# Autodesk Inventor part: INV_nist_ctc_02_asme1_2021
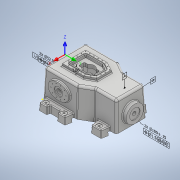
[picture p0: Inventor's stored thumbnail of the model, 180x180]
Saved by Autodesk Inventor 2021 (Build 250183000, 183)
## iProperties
Created: 2016-11
Part Number: INV_nist_ctc_02_asme1_2021
Material: Generic
Document SubType Name: Modeling
Designer: t_liuje
Density: 1 g/cm^3
Appearance: Default
Author: t_liuje
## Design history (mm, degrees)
node "Coaxial Axes Pattern 1"
node "Coaxial Axes Pattern 2"
  node "Simple Hole 17"
  node "Simple Hole 18"
  node "Hole Note 14"
  node "Feature Control Frame 49"
node "Coplanar Group 1" dims "d446" = 2.3385 (derived), "d447" = 8.09976 (derived), "d525" = 52.99059 (derived), "d527" = 0.05 (derived), "d528" = 0 (derived), "d529" = 0 (derived), "d545" = 21.5915 (derived), "d547" = 0.05 (derived), "d548" = 0 (derived), "d549" = 0 (derived), "d560" = 7.29892 (derived), "d561" = 5.22182 (derived), "d562" = 0.5 (derived), "d563" = 0 (derived), "d564" = 0 (derived), "d565" = 4.43129 (derived), "d566" = 0.05984 (derived), "d567" = 0.5 (derived), "d568" = 0 (derived), "d569" = 0 (derived), "d570" = 3.72166 (derived), "d571" = 0.83718 (derived), "d572" = 0.5 (derived), "d573" = 0 (derived)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
  node "Planar Surface 24"
  node "Planar Surface 25"
  node "Planar Surface 26"
  node "Planar Surface 27"
  node "Feature Control Frame 52"
  node "Datum Identifier 26" dims "d446" = 2.3385 (derived), "d447" = 8.09976 (derived), "d525" = 52.99059 (derived), "d527" = 0.05 (derived), "d528" = 0 (derived), "d529" = 0 (derived), "d545" = 21.5915 (derived), "d547" = 0.05 (derived), "d548" = 0 (derived), "d549" = 0 (derived), "d560" = 7.29892 (derived), "d561" = 5.22182 (derived), "d562" = 0.5 (derived), "d563" = 0 (derived), "d564" = 0 (derived), "d565" = 4.43129 (derived), "d566" = 0.05984 (derived), "d567" = 0.5 (derived), "d568" = 0 (derived), "d569" = 0 (derived), "d570" = 3.72166 (derived), "d571" = 0.83718 (derived), "d572" = 0.5 (derived), "d573" = 0 (derived)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
  node "Leader Text 1"
node "Datum Reference Frame 28"
node "Simple Hole 19" dims "d446" = 2.3385 (derived), "d447" = 8.09976 (derived), "d525" = 52.99059 (derived), "d527" = 0.05 (derived), "d528" = 0 (derived), "d529" = 0 (derived), "d545" = 21.5915 (derived), "d547" = 0.05 (derived), "d548" = 0 (derived), "d549" = 0 (derived), "d560" = 7.29892 (derived), "d561" = 5.22182 (derived), "d562" = 0.5 (derived), "d563" = 0 (derived), "d564" = 0 (derived), "d565" = 4.43129 (derived), "d566" = 0.05984 (derived), "d567" = 0.5 (derived), "d568" = 0 (derived), "d569" = 0 (derived), "d570" = 3.72166 (derived), "d571" = 0.83718 (derived), "d572" = 0.5 (derived), "d573" = 0 (derived)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
  node "Feature Control Frame 60"
  node "Datum Identifier 30" dims "d446" = 2.3385 (derived), "d447" = 8.09976 (derived), "d525" = 52.99059 (derived), "d527" = 0.05 (derived), "d528" = 0 (derived), "d529" = 0 (derived), "d545" = 21.5915 (derived), "d547" = 0.05 (derived), "d548" = 0 (derived), "d549" = 0 (derived), "d560" = 7.29892 (derived), "d561" = 5.22182 (derived), "d562" = 0.5 (derived), "d563" = 0 (derived), "d564" = 0 (derived), "d565" = 4.43129 (derived), "d566" = 0.05984 (derived), "d567" = 0.5 (derived), "d568" = 0 (derived), "d569" = 0 (derived), "d570" = 3.72166 (derived), "d571" = 0.83718 (derived), "d572" = 0.5 (derived), "d573" = 0 (derived)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
node "Datum Reference Frame 29"
node "Datum Reference Frame 30"
node "Simple Hole 20" dims "d446" = 2.3385 (derived), "d447" = 8.09976 (derived), "d525" = 52.99059 (derived), "d527" = 0.05 (derived), "d528" = 0 (derived), "d529" = 0 (derived), "d545" = 21.5915 (derived), "d547" = 0.05 (derived), "d548" = 0 (derived), "d549" = 0 (derived), "d560" = 7.29892 (derived), "d561" = 5.22182 (derived), "d562" = 0.5 (derived), "d563" = 0 (derived), "d564" = 0 (derived), "d565" = 4.43129 (derived), "d566" = 0.05984 (derived), "d567" = 0.5 (derived), "d568" = 0 (derived), "d569" = 0 (derived), "d570" = 3.72166 (derived), "d571" = 0.83718 (derived), "d572" = 0.5 (derived), "d573" = 0 (derived)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
  node "Feature Control Frame 61"
  node "Datum Identifier 31" dims "d446" = 2.3385 (derived), "d447" = 8.09976 (derived), "d525" = 52.99059 (derived), "d527" = 0.05 (derived), "d528" = 0 (derived), "d529" = 0 (derived), "d545" = 21.5915 (derived), "d547" = 0.05 (derived), "d548" = 0 (derived), "d549" = 0 (derived), "d560" = 7.29892 (derived), "d561" = 5.22182 (derived), "d562" = 0.5 (derived), "d563" = 0 (derived), "d564" = 0 (derived), "d565" = 4.43129 (derived), "d566" = 0.05984 (derived), "d567" = 0.5 (derived), "d568" = 0 (derived), "d569" = 0 (derived), "d570" = 3.72166 (derived), "d571" = 0.83718 (derived), "d572" = 0.5 (derived), "d573" = 0 (derived)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
node "Datum Reference Frame 31"
node "Datum Reference Frame 33"
node "Datum Reference Frame 35"
node "Datum Reference Frame 32"
node "Datum Reference Frame 34"
node "Planar Surface 28"
  node "Feature Control Frame 55"
node "Planar Surface 29"
  node "Feature Control Frame 56"
node "Planar Surface 30"
  node "Feature Control Frame 58"
node "Planar Surface 31"
  node "Feature Control Frame 59"
body "Solid1"
node "Blocks"
node "Annotations"
node "Tolerance Features"
sketch "Sketch1"
  geometry: L1 (0, 0)-(400, 0); L2 (400, 500)-(0, 500); L3 (0, 500)-(0, 0); L4 (529.904, 425)-(780, 425); L5 (780, 425)-(780, 75); L6 (780, 75)-(529.904, 75); L7 (400, 500)-(529.904, 425); L8 (400, 0)-(529.904, 75)
  constraints: 16 end point, 3 parallel, 2 horizontal, 1 perpendicular, 1 vertical
  dimensions: "d0" = 400 distance of L2.end L2.start; "d3" = 350 distance of L4.end L5.end; "d4" = 75 distance between parallel lines of L1 L6; "d5" = 150 deg angle of L2 L7; "d6" = 150 deg angle of L1 L8 (= d5); "d8" = 500 distance of L2.end L1.start; "d9" = 380 distance from line of L5 L2.start
extrude "Extrusion1" new body sketch "Sketch1" distance "d10" = 330; taper "d11" = 0 deg
feature "FaceDraft1" dims angle "d12" = -2 deg
shell "Shell1" dims "d171" = 40
fillet "Fillet1" dims "d670" = 25
sketch "Sketch2"
  geometry: L1 (115, 385)-(365, 385); L2 (465, 332.499)-(465, 167.501); L3 (365, 115)-(115, 115); L4 (115, 115)-(115, 385); L5 (0, 0)-(400, 0) reference; L6 (0, 500)-(0, 0) reference; L7 (365, 385)-(465, 332.499); L8 (365, 115)-(465, 167.501); L9 (353.905, 340)-(160, 340); L10 (160, 340)-(160, 160); L11 (160, 160)-(353.905, 160); L12 (353.905, 160)-(420, 194.7); L13 (420, 194.7)-(420, 305.3); L14 (420, 305.3)-(353.905, 340); 4 further points
  constraints: 24 end point, 4 parallel, 2 perpendicular, 1 horizontal, 5 other
  dimensions: "d16" = 115 distance between parallel lines of L5 L3; "d17" = 115 distance between parallel lines of L6 L4; "d18" = 100 distance from line of L1.end L2; "d19" = 152.3 deg angle of L1 L7; "d22" = 270 distance between parallel lines of L1 L3; "d23" = 350 distance between parallel lines of L4 L2; "d24" = 152.3 deg angle of L3 L8; "d25" = 100 distance from line of L2 L3.start (= d18); "d26" = 45 distance between parallel lines of L1 L9
extrude "Extrusion2" join sketch "Sketch2" distance "d27" = 30; taper "d28" = 0 deg
fillet "Fillet2" dims "d29" = 8
sketch "Sketch3"
  geometry: L1 (355.652, 339.083)-(415.719, 307.547) reference; L2 (420, 300.464)-(420, 199.536) reference; L3 (415.719, 192.453)-(355.652, 160.917) reference; L4 (351.933, 160)-(168, 160) reference; L5 (160, 168)-(160, 332) reference; L6 (168, 340)-(351.933, 340) reference; L7 (365, 385)-(115, 385) reference; L8 (115, 385)-(115, 115) reference; L9 (115, 115)-(365, 115) reference; L10 (365, 115)-(465, 167.501) reference; L11 (465, 167.501)-(465, 332.499) reference; L12 (465, 332.499)-(365, 385) reference; L13 (351.933, 351)-(168, 351); L14 (149, 332)-(149, 168); L15 (168, 149)-(351.933, 149); L16 (360.765, 151.178)-(420.832, 182.713); L17 (431, 199.536)-(431, 300.464); L18 (420.832, 317.287)-(360.765, 348.822); L19 (168, 359)-(351.933, 359); L20 (364.484, 355.906)-(424.551, 324.37); L21 (439, 300.464)-(439, 199.536); L22 (424.551, 175.63)-(364.484, 144.094); L23 (351.933, 141)-(168, 141); L24 (141, 168)-(141, 332); A1 r 8 centre (412, 300.464) between (420, 300.464) and (415.719, 307.547) reference; A2 r 8 centre (412, 199.536) between (415.719, 192.453) and (420, 199.536) reference; A3 r 8 centre (351.933, 168) between (351.933, 160) and (355.652, 160.917) reference; A4 r 8 centre (168, 168) between (160, 168) and (168, 160) reference; A5 r 8 centre (168, 332) between (168, 340) and (160, 332) reference; A6 r 8 centre (351.933, 332) between (355.652, 339.083) and (351.933, 340) reference; A7 r 19 centre (168, 332) between (168, 351) and (149, 332); A8 r 19 centre (168, 168) between (149, 168) and (168, 149); A9 r 19 centre (351.933, 168) between (351.933, 149) and (360.765, 151.178); A10 r 19 centre (412, 199.536) between (420.832, 182.713) and (431, 199.536); A11 r 19 centre (412, 300.464) between (431, 300.464) and (420.832, 317.287); A12 r 19 centre (351.933, 332) between (360.765, 348.822) and (351.933, 351); A13 r 27 centre (351.933, 332) between (364.484, 355.906) and (351.933, 359); A14 r 27 centre (412, 300.464) between (439, 300.464) and (424.551, 324.37); A15 r 27 centre (412, 199.536) between (424.551, 175.63) and (439, 199.536); A16 r 27 centre (351.933, 168) between (351.933, 141) and (364.484, 144.094); A17 r 27 centre (168, 168) between (141, 168) and (168, 141); A18 r 27 centre (168, 332) between (168, 359) and (141, 332); 1 further point
  constraints: 24 end point, 24 point on circle, 12 centre point, 22 other
  dimensions: "d30" = 11 distance between parallel lines of L6 L13; "d31" = 8 distance between parallel lines of L13 L19
extrude "Extrusion3" cut sketch "Sketch3" distance "d32" = 8; taper "d33" = 0 deg
hole "Hole1" diameter "d36" = 8.38; stored, may be unused: countersink angle "d40" = 90 deg, drill point angle "d42" = 0 deg; dims "d34" = 13, "d35" = 13, "d37" = 6, "d38" = 4, "d39" = 2, "d41" = 25
hole "Hole2" diameter "d51" = 8.38; stored, may be unused: countersink angle "d55" = 90 deg, drill point angle "d57" = 0 deg; dims "d49" = 61, "d50" = 13, "d52" = 6, "d53" = 4, "d54" = 2, "d56" = 25
hole "Hole3" diameter "d60" = 8.38; stored, may be unused: countersink angle "d64" = 90 deg, drill point angle "d66" = 0 deg; dims "d58" = 13, "d59" = 110, "d61" = 6, "d62" = 4, "d63" = 2, "d65" = 25
hole "Hole4" diameter "d69" = 8.38; stored, may be unused: countersink angle "d73" = 90 deg, drill point angle "d75" = 0 deg; dims "d67" = 13, "d68" = 160, "d70" = 6, "d71" = 4, "d72" = 2, "d74" = 25
hole "Hole5" diameter "d78" = 8.38; stored, may be unused: countersink angle "d82" = 90 deg, drill point angle "d84" = 0 deg; dims "d76" = 13, "d77" = 61, "d79" = 6, "d80" = 4, "d81" = 2, "d83" = 25
pattern_linear "Rectangular Pattern3" dims "d87" = 48
hole "Hole6" diameter "d90" = 8.38; stored, may be unused: countersink angle "d94" = 90 deg, drill point angle "d96" = 0 deg; dims "d88" = 13, "d89" = 13, "d91" = 6, "d92" = 4, "d93" = 2, "d95" = 25
hole "Hole7" diameter "d99" = 8.38; stored, may be unused: countersink angle "d103" = 90 deg, drill point angle "d105" = 0 deg; dims "d97" = 13, "d98" = 13, "d100" = 6, "d101" = 4, "d102" = 2, "d104" = 25
pattern_linear "Rectangular Pattern4" dims "d117" = 50.9055
hole "Hole9" diameter "d120" = 8.38; stored, may be unused: countersink angle "d124" = 90 deg, drill point angle "d126" = 0 deg; dims "d118" = 13, "d119" = 61, "d121" = 6, "d122" = 4, "d123" = 2, "d125" = 25
pattern_linear "Rectangular Pattern5" dims "d129" = 48
hole "Hole10" diameter "d132" = 8.38; stored, may be unused: countersink angle "d136" = 90 deg, drill point angle "d138" = 0 deg; dims "d130" = 13, "d131" = 13, "d133" = 6, "d134" = 4, "d135" = 2, "d137" = 25
hole "Hole11" diameter "d141" = 8.38; stored, may be unused: countersink angle "d145" = 90 deg, drill point angle "d147" = 0 deg; dims "d139" = 13, "d140" = 13, "d142" = 6, "d143" = 4, "d144" = 2, "d146" = 25
pattern_linear "Rectangular Pattern6" dims "d150" = 50.9055
hole "Hole12" diameter "d153" = 8.38; stored, may be unused: countersink angle "d157" = 90 deg, drill point angle "d159" = 0 deg; dims "d151" = 13, "d152" = 65, "d154" = 6, "d155" = 4, "d156" = 2, "d158" = 25
hole "Hole13" diameter "d162" = 8.38; stored, may be unused: countersink angle "d166" = 90 deg, drill point angle "d168" = 0 deg; dims "d160" = 13, "d161" = 65, "d163" = 6, "d164" = 4, "d165" = 2, "d167" = 25
feature "FaceDraft2" dims angle "d169" = 2 deg
feature "FaceDraft3" dims angle "d170" = 2 deg
fillet "Fillet3" dims "d172" = 25
sketch "Sketch5"
  geometry: L1 (0.093, 195.706)-(0.093, 155.706); L2 (180.093, 155.706)-(180.093, 195.706); L3 (180.093, 210.706)-(0.093, 140.706); L4 (0.093, 210.706)-(180.093, 140.706); L5 (380.093, 400.722)-(380.093, -74.294) reference; L6 (380.093, -74.294)-(-13.212, -74.294) reference; L7 (15.093, 140.706)-(41.359, 140.706); L8 (138.827, 140.706)-(165.093, 140.706); L9 (165.093, 210.706)-(138.827, 210.706); L10 (41.359, 210.706)-(15.093, 210.706); A1 r 60 centre (90.093, 175.706) between (138.827, 210.706) and (41.359, 210.706); A2 r 60 centre (90.093, 175.706) between (41.359, 140.706) and (138.827, 140.706); A3 r 15 centre (165.093, 155.706) between (165.093, 140.706) and (180.093, 155.706); A4 r 15 centre (165.093, 195.706) between (180.093, 195.706) and (165.093, 210.706); A5 r 15 centre (15.093, 195.706) between (15.093, 210.706) and (0.093, 195.706); A6 r 15 centre (15.093, 155.706) between (0.093, 155.706) and (15.093, 140.706); 5 further points
  constraints: 16 end point, 12 point on circle, 8 point on line, 8 tangent, 6 centre point, 5 parallel, 2 equal radius, 2 horizontal, 2 midpoint, 2 perpendicular, 1 coincident
  dimensions: "d173" = 180 distance of L4.end L3.end; "d174" = 70 distance of L3.end L4.start; "d175" = 200 distance between parallel lines of L2 L5; "d178" = 15 radius of A3; "d179" = 15 radius of A6 (derived)
extrude "Extrusion4" cut sketch "Sketch5" stored distance "d180" = 8; taper "d181" = 0 deg
workplane "Work Plane2"
workplane "Work Plane4"
sketch "Sketch6"
  geometry: L1 (99.985, 0)-(400.015, 0) reference; C1 r 100 at (250, 140); 3 further points
  constraints: 1 centre point
  dimensions: "d186" = 200 diameter of C1; "d187" = 140 distance from line of L1 C1.centre; "d188" = 250 horizontal distance of point (0, 0) C1.centre
extrude "Extrusion5" join sketch "Sketch6" stored distance "d189" = 8; taper "d190" = 0 deg
sketch "Sketch7"
  geometry: L1 (475.015, 0)-(0, 0) reference; C1 r 100 at (250, 140); 2 further points
  constraints: 1 centre point
  dimensions: "d191" = 200 diameter of C1; "d192" = 250 horizontal distance of C1.centre L1.end; "d193" = 140 distance from line of C1.centre L1
extrude "Extrusion6" join sketch "Sketch7" stored distance "d194" = 8; taper "d195" = 0 deg
hole "Hole14" diameter "d198" = 120; stored, may be unused: countersink angle "d202" = 90 deg, drill point angle "d204" = 0 deg; dims "d196" = 10, "d197" = 10, "d199" = 6, "d200" = 4, "d201" = 2, "d203" = 8
hole "Hole15" diameter "d207" = 120; stored, may be unused: countersink angle "d211" = 90 deg, drill point angle "d213" = 0 deg; dims "d205" = 10, "d206" = 10, "d208" = 6, "d209" = 4, "d210" = 2, "d212" = 8
hole "Hole16" diameter "d216" = 40; stored, may be unused: countersink angle "d220" = 90 deg, drill point angle "d222" = 0 deg; dims "d217" = 6, "d218" = 4, "d219" = 2, "d221" = 8, "d722" = 10, "d723" = 10
hole "Hole17" diameter "d225" = 117; stored, may be unused: countersink angle "d229" = 90 deg, drill point angle "d231" = 0 deg; dims "d226" = 6, "d227" = 4, "d228" = 2, "d230" = 18, "d241" = 10, "d242" = 10
hole "Hole18" diameter "d234" = 70; stored, may be unused: countersink angle "d238" = 90 deg, drill point angle "d240" = 0 deg; dims "d235" = 6, "d236" = 4, "d237" = 2, "d239" = 8, "d243" = 10, "d244" = 10
hole "Hole19" diameter "d247" = 115; stored, may be unused: countersink angle "d251" = 90 deg, drill point angle "d253" = 0 deg; dims "d245" = 10, "d246" = 10, "d248" = 6, "d249" = 4, "d250" = 2, "d252" = 18
hole "Hole20" diameter "d256" = 85; stored, may be unused: countersink angle "d260" = 90 deg, drill point angle "d262" = 0 deg; dims "d257" = 6, "d258" = 4, "d259" = 2, "d261" = 8, "d615" = 10, "d616" = 10
sketch "Sketch8" dims "d263" = 120, "d264" = 90
  geometry: L1 (-390.443, 330)-(-35.666, 330) reference; 2 further points; 1 other entity
  constraints: 2 other
  dimensions: "d265" = 200 horizontal distance of point (0, 0) point (-200, 185); "d781" = 145 distance from line of L1 point (-200, 185)
extrude "Extrusion7" join sketch "Sketch8" stored distance "d267" = 8; taper "d268" = 0 deg
fillet "Fillet4" dims "d269" = 10
sketch "Sketch9" dims "d270" = 72, "d271" = 88
  geometry: L1 (112, 185)-(288, 185); L2 (131.502, 230.2)-(268.498, 139.8); L3 (268.498, 230.2)-(131.502, 139.8); L4 (175.273, 254.099)-(224.727, 115.901); L5 (175.285, 115.898)-(224.715, 254.102); C1 r 4.19 at (131.502, 230.2); C2 r 4.19 at (112, 185); C3 r 4.19 at (175.273, 254.099); C4 r 4.19 at (224.715, 254.102); C5 r 4.19 at (288, 185); C6 r 4.19 at (268.498, 139.8); C7 r 4.19 at (224.727, 115.901); C8 r 4.19 at (175.285, 115.898); C9 r 4.19 at (131.502, 139.8); C10 r 4.19 at (268.498, 230.2); 8 further points; 1 other entity
  constraints: 10 centre point, 10 end point, 8 midpoint, 3 coincident, 1 horizontal, 13 other
  dimensions: "d283" = 200 horizontal distance of point (0, 0) point (200, 185) (derived); "d284" = 185 vertical distance of point (0, 0) point (200, 185) (derived); "d285" = 33.42 deg angle of L1 L2; "d286" = 36.89 deg angle of L2 L4; "d287" = 39.37 deg angle of L4 L5; "d288" = 8.38 diameter of C1; "d289" = 8.38 diameter of C2; "d290" = 8.38 diameter of C3; "d291" = 8.38 diameter of C4; "d293" = 8.38 diameter of C5; "d294" = 8.38 diameter of C6; "d295" = 8.38 diameter of C7; "d297" = 8.38 diameter of C8; "d298" = 33.42 deg angle of L3 L1 (derived); "d299" = 8.38 diameter of C9; "d300" = 8.38 diameter of C10
extrude "Extrusion8" cut sketch "Sketch9" distance "d301" = 21; taper "d302" = 0 deg
sketch "Sketch10"
  geometry: C1 r 50 at (200, 185); 2 further points; 1 other entity
  constraints: 1 centre point, 1 coincident, 1 other
  dimensions: "d303" = 100 diameter of C1
extrude "Extrusion9" cut sketch "Sketch10" distance "d304" = 8; taper "d305" = 0 deg
hole "Hole21" diameter "d308" = 52; stored, may be unused: countersink angle "d312" = 90 deg, drill point angle "d314" = 0 deg; dims "d309" = 6, "d310" = 4, "d311" = 2, "d313" = 8, "d868" = 10, "d869" = 10
workplane "Work Plane5"
workplane "Work Plane6"
mirror "Mirror1"
fillet "Fillet5" dims "d316" = 10
workplane "Work Plane7"
sketch "Sketch11"
  geometry: L1 (0, 0)-(-393.305, 0) reference; L2 (-50, -90)-(-350, -90); L3 (-200, -202.49)-(-200, 149); L4 (-168, 149)-(-351.933, 149) reference; L5 (0, 475.015)-(0, 0) reference; L6 (-350, -90)-(-369.101, 18.329); L7 (-350, -90)-(-240, -90); L8 (-50, -90)-(-30.899, 18.329); L9 (-50, -90)-(-140, -90); L10 (-140, -90)-(-146.171, -55); L11 (-260, -90)-(-253.829, -55); L12 (-146.171, -55)-(-253.829, -55); L13 (-350, -90)-(-260, -90); L14 (-30.899, 18.329)-(-369.101, 18.329); C1 r 11 at (-305, -55); C2 r 11 at (-95, -55); 4 further points
  constraints: 22 end point, 5 symmetric about line, 4 horizontal, 2 centre point, 2 point on line, 1 collinear, 1 equal length, 1 vertical, 1 other
  dimensions: "d320" = 90 distance between parallel lines of L1 L2; "d321" = 300 distance of L2.start L2.end; "d322" = 200 distance between parallel lines of L5 L3; "d323" = 110 distance of L2.end L6.end; "d324" = 100 deg angle of L7 L6; "d325" = 22 diameter of C1; "d326" = 105 distance from line of C1.centre L3; "d327" = 35 distance from line of C1.centre L2; "d328" = 90 distance of L2.start L9.end; "d329" = 100 deg angle of L9 L10; "d330" = 35 distance from line of L9 L10.end
extrude "Extrusion10" join sketch "Sketch11" distance "d332" = 81; taper "d333" = 0 deg
feature "FaceDraft4" dims angle "d334" = -3 deg
feature "FaceDraft5" dims angle "d335" = 5 deg
fillet "Fillet6" dims "d336" = 10
sketch "Sketch12"
  geometry: L1 (-18.148, -20)-(-380.725, -20); L2 (-380.725, -20)-(-380.725, 18.329); L3 (-380.725, 18.329)-(-18.148, 18.329); L4 (-18.148, 18.329)-(-18.148, -20); L5 (-372.128, 0)-(-27.872, 0) reference; L6 (-30.899, 18.329)-(-369.101, 18.329) reference; 2 further points
  constraints: 8 end point, 2 parallel, 1 collinear, 1 horizontal, 1 perpendicular
  dimensions: "d337" = 20 distance between parallel lines of L5 L1
extrude "Extrusion11" cut sketch "Sketch12" stored distance "d338" = 81; taper "d339" = 0 deg
fillet "Fillet7" dims "d340" = 6
sketch "Sketch13"
  geometry: L1 (-635, -70.886)-(-635, 169.685); L2 (-780, 99.985)-(-780, 400.015) reference; L3 (-577, -15)-(-693, -15); L4 (-536.598, 75)-(-755.015, 75) reference; L5 (-577, -15)-(-557.899, 93.329); L6 (-577, -15)-(-467, -15); L7 (-693, -15)-(-712.101, 93.329); L8 (-557.899, 93.329)-(-712.101, 93.329); C1 r 11 at (-635, 20); 4 further points
  constraints: 12 end point, 3 horizontal, 2 symmetric about line, 1 centre point, 1 equal length, 1 point on line, 1 vertical
  dimensions: "d341" = 145 distance between parallel lines of L1 L2; "d342" = 116 distance of L3.start L3.end; "d343" = 90 distance between parallel lines of L4 L3; "d344" = 110 distance of L3.start L5.end; "d345" = 80 deg angle of L6 L5; "d346" = 22 diameter of C1; "d347" = 35 distance from line of C1.centre L3
extrude "Extrusion12" join sketch "Sketch13" distance "d348" = 81; taper "d349" = 0 deg
feature "FaceDraft6" dims angle "d350" = -3 deg
feature "FaceDraft7" dims angle "d351" = 5 deg
fillet "Fillet8" dims "d352" = 10
sketch "Sketch14"
  geometry: L1 (-538.713, 55)-(-738.472, 55); L2 (-738.472, 55)-(-738.472, 93.329); L3 (-738.472, 93.329)-(-538.713, 93.329); L4 (-538.713, 93.329)-(-538.713, 55); L5 (-712.101, 93.329)-(-557.899, 93.329) reference; L6 (-715.128, 75)-(-554.872, 75) reference; 2 further points
  constraints: 8 end point, 2 parallel, 1 collinear, 1 horizontal, 1 perpendicular
  dimensions: "d353" = 20 distance between parallel lines of L1 L6
extrude "Extrusion13" cut sketch "Sketch14" stored distance "d354" = 81; taper "d355" = 0 deg
fillet "Fillet9" dims "d356" = 6
workplane "Work Plane9"
sketch "Sketch15"
  geometry: C1 r 11 at (-635, 20) reference; C2 r 30 at (-635, 20); 1 further point
  constraints: 1 centre point, 1 coincident
  dimensions: "d358" = 60 diameter of C2
extrude "Extrusion14" cut sketch "Sketch15" stored distance "d359" = 10; taper "d360" = 0 deg
workplane "Work Plane10"
sketch "Sketch16"
  geometry: C1 r 11 at (-95, -55) reference; C2 r 30 at (-95, -55); C3 r 11 at (-305, -55) reference; C4 r 30 at (-305, -55); 1 further point
  constraints: 2 centre point, 2 coincident
  dimensions: "d362" = 60 diameter of C2; "d363" = 60 diameter of C4
extrude "Extrusion15" cut sketch "Sketch16" stored distance "d364" = 81; taper "d365" = 0 deg
mirror "Mirror2"
hole "Hole22" diameter "d368" = 10.1; stored, may be unused: countersink angle "d372" = 90 deg, drill point angle "d374" = 118 deg; dims "d366" = 62.5, "d367" = 20, "d369" = 6, "d370" = 4, "d371" = 2, "d373" = 30
hole "Hole23" diameter "d380" = 10.1; stored, may be unused: countersink angle "d384" = 90 deg, drill point angle "d386" = 118 deg; dims "d378" = 20, "d379" = 60, "d381" = 6, "d382" = 4, "d383" = 2, "d385" = 30
pattern_linear "Rectangular Pattern8" dims "d389" = 75
hole "Hole24" diameter "d392" = 12; stored, may be unused: countersink angle "d396" = 90 deg, drill point angle "d398" = 118 deg; dims "d390" = 34, "d391" = 25, "d393" = 6, "d394" = 4, "d395" = 2, "d397" = 25
hole "Hole25" diameter "d401" = 12; stored, may be unused: countersink angle "d405" = 90 deg, drill point angle "d407" = 118 deg; dims "d399" = 25, "d400" = 25, "d402" = 6, "d403" = 4, "d404" = 2, "d406" = 25
hole "Hole26" diameter "d410" = 10.1; stored, may be unused: countersink angle "d414" = 90 deg, drill point angle "d416" = 118 deg; dims "d408" = 62.5, "d409" = 20, "d411" = 6, "d412" = 4, "d413" = 2, "d415" = 30
hole "Hole27" diameter "d422" = 10.1; stored, may be unused: countersink angle "d426" = 90 deg, drill point angle "d428" = 118 deg; dims "d420" = 20, "d421" = 70, "d423" = 6, "d424" = 4, "d425" = 2, "d427" = 30
pattern_linear "Rectangular Pattern10" dims "d431" = 75
hole "Hole28" diameter "d434" = 10.1; stored, may be unused: countersink angle "d438" = 90 deg, drill point angle "d440" = 118 deg; dims "d432" = 20, "d433" = 435, "d435" = 6, "d436" = 4, "d437" = 2, "d439" = 30
mirror "Mirror3"
fillet "Fillet10" dims "d664" = 10
fillet "Fillet11" dims "d669" = 10
sketch "Sketch18"
  geometry: 1 further point
sketch "Sketch19"
  geometry: L1 (0, 450.03)-(0, 0) reference
  dimensions: "d777" = 15 dimension on L1; "d778" = 18.148 dimension on L1.end
workplane "Work Plane13"
sketch "Sketch20"
  geometry: C1 r 26 at (-16.323, -80.872) reference; C2 r 57.5 at (-16.323, -80.872); 1 further point
  constraints: 1 centre point, 1 coincident
  dimensions: "d677" = 115 diameter of C2
extrude "Extrusion18" cut sketch "Sketch20" distance "d678" = 20; taper "d679" = 0 deg
mirror "Mirror5"
fillet "Fillet13" dims "d681" = 10
sketch "Sketch21"
  geometry: L1 (156.902, 386.513)-(56.912, 385.065); 1 further point
  constraints: 2 end point
  dimensions: "d689" = 100 distance of L1.start L1.end
hole "Hole29" diameter "d726" = 40; stored, may be unused: countersink angle "d730" = 90 deg, drill point angle "d732" = 118 deg; dims "d724" = 10, "d725" = 10, "d727" = 6, "d728" = 4, "d729" = 2, "d731" = 8
extrude "Extrusion19" cut sketch "Sketch19" distance "d779" = 2; taper "d780" = 0 deg
sketch "Sketch22" dims "d245" = 10, "d246" = 10
  geometry: L1 (-30.052, -30.052)-(30.052, 30.052); L2 (-36.279, -22.137)-(22.137, 36.279); L3 (-40.659, -12.374)-(12.374, 40.659); L4 (-42.5, -0.074)-(0.074, 42.5); L5 (-38.439, 18.129)-(-18.129, 38.439); L6 (-22.137, -36.279)-(36.279, 22.137); L7 (-12.374, -40.659)-(40.659, 12.374); L8 (-0.074, -42.5)-(42.5, 0.074); L9 (18.129, -38.439)-(38.439, -18.129); 2 further points
  constraints: 18 end point, 8 parallel, 1 midpoint, 20 other
  dimensions: "d829" = 10 distance between parallel lines of L1 L2; "d830" = 10 distance between parallel lines of L2 L3; "d831" = 10 distance between parallel lines of L3 L4; "d832" = 10 distance between parallel lines of L4 L5; "d833" = 10 distance between parallel lines of L1 L6; "d834" = 10 distance between parallel lines of L6 L7; "d835" = 10 distance between parallel lines of L7 L8; "d836" = 10 distance between parallel lines of L8 L9
node "Projected Loop1"
workplane "Work Plane1"
workplane "Work Plane3"
workplane "Work Plane11"
workplane "Work Plane12"
sketch "Block1"
  geometry: L1 (56.833, -28.413)-(59.965, -28.413); L2 (59.965, -28.413)-(59.965, -17.004); L3 (60.683, -16.688)-(70.948, -27.789); L4 (76.603, -25.575)-(76.603, -13.412); L5 (76.603, -13.412)-(73.5, -13.412); L6 (73.5, -13.412)-(73.5, -24.656); L7 (72.563, -25.022)-(63.096, -14.732); L8 (56.833, -16.93)-(56.833, -28.413); L9 (51.689, -17.608)-(51.689, -28.413); L10 (51.689, -28.413)-(54.822, -28.413); L11 (54.822, -28.413)-(54.822, -17.608); L12 (50.626, -13.412)-(35.425, -13.412); L13 (35.425, -22.435)-(45.052, -22.435); L14 (44.937, -25.251)-(29.247, -25.251); L15 (29.247, -25.251)-(29.247, -13.412); L16 (29.247, -13.412)-(26.145, -13.412); L17 (26.145, -13.412)-(26.145, -25.251); L18 (26.145, -25.251)-(19.735, -25.251); L19 (19.735, -25.251)-(19.735, -28.413); L20 (19.735, -28.413)-(45.339, -28.413); L21 (44.995, -19.332)-(35.943, -19.332); L22 (35.885, -16.516)-(50.597, -16.516); L23 (56.833, -28.412)-(59.965, -28.412); L24 (56.833, -16.93)-(56.833, -28.412); L25 (72.563, -25.022)-(63.096, -14.732); L26 (73.5, -13.413)-(73.5, -24.656); L27 (76.603, -13.413)-(73.5, -13.413); L28 (76.603, -25.575)-(76.603, -13.413); L29 (60.683, -16.688)-(70.948, -27.789); L30 (59.965, -28.412)-(59.965, -17.004); L31 (51.689, -17.608)-(51.689, -28.412); L32 (35.885, -16.516)-(50.597, -16.516); L33 (44.995, -19.332)-(35.943, -19.332); L34 (19.735, -28.412)-(45.339, -28.412); L35 (19.735, -25.251)-(19.735, -28.412); L36 (26.145, -25.251)-(19.735, -25.251); L37 (26.145, -13.413)-(26.145, -25.251); L38 (29.247, -13.413)-(26.145, -13.413); L39 (29.247, -25.251)-(29.247, -13.413); L40 (44.937, -25.251)-(29.247, -25.251); L41 (35.425, -22.435)-(45.052, -22.435); L42 (50.626, -13.413)-(35.425, -13.413); L43 (54.822, -28.412)-(54.822, -17.608); L44 (51.689, -28.412)-(54.822, -28.412); A1 r 0.415 centre (60.378, -16.97) between (60.683, -16.688) and (59.965, -17.004); A2 r 3.261 centre (73.342, -25.575) between (70.948, -27.789) and (76.603, -25.575); A3 r 0.54 centre (72.96, -24.656) between (72.563, -25.022) and (73.5, -24.656); A4 r 3.517 centre (60.35, -16.93) between (63.096, -14.732) and (56.833, -16.93); A5 r 4.196 centre (50.626, -17.608) between (54.822, -17.608) and (50.626, -13.412); A6 r 4.568 centre (36.144, -17.924) between (35.425, -13.412) and (35.425, -22.435); A7 r 1.41 centre (45.052, -23.846) between (44.937, -25.251) and (45.052, -22.435); A8 r 4.547 centre (45.339, -23.866) between (45.339, -28.413) and (44.995, -19.332); A9 r 1.417 centre (36.066, -17.921) between (35.885, -16.516) and (35.943, -19.332); A10 r 1.093 centre (50.597, -17.608) between (51.689, -17.608) and (50.597, -16.516); A11 r 3.517 centre (60.35, -16.93) between (63.096, -14.732) and (56.833, -16.93); A12 r 0.54 centre (72.96, -24.656) between (72.563, -25.022) and (73.5, -24.656); A13 r 3.261 centre (73.342, -25.575) between (70.948, -27.789) and (76.603, -25.575); A14 r 0.415 centre (60.378, -16.97) between (60.683, -16.688) and (59.965, -17.004); A15 r 1.093 centre (50.597, -17.608) between (51.689, -17.608) and (50.597, -16.516); A16 r 1.417 centre (36.066, -17.921) between (35.885, -16.516) and (35.943, -19.332); A17 r 4.547 centre (45.339, -23.866) between (45.339, -28.412) and (44.995, -19.332); A18 r 1.41 centre (45.052, -23.846) between (44.937, -25.251) and (45.052, -22.435); A19 r 4.568 centre (36.144, -17.924) between (35.425, -13.413) and (35.425, -22.435); A20 r 4.196 centre (50.626, -17.608) between (54.822, -17.608) and (50.626, -13.413); 1 further point
  constraints: 88 end point, 40 point on circle, 20 centre point
workplane "Work Plane15"
sketch "Block7"
  geometry: L1 (30, 55.245)-(30, 58.378); L2 (30, 58.378)-(18.592, 58.378); L3 (18.276, 59.095)-(29.376, 69.36); L4 (27.162, 75.015)-(15, 75.015); L5 (15, 75.015)-(15, 71.913); L6 (15, 71.913)-(26.243, 71.913); L7 (26.609, 70.976)-(16.319, 61.509); L8 (18.517, 55.245)-(30, 55.245); L9 (19.196, 50.102)-(30, 50.102); L10 (30, 50.102)-(30, 53.234); L11 (30, 53.234)-(19.196, 53.234); L12 (15, 49.039)-(15, 33.838); L13 (24.023, 33.838)-(24.023, 43.465); L14 (26.839, 43.35)-(26.839, 27.66); L15 (26.839, 27.66)-(15, 27.66); L16 (15, 27.66)-(15, 24.557); L17 (15, 24.557)-(26.839, 24.557); L18 (26.839, 24.557)-(26.839, 18.148); L19 (26.839, 18.148)-(30, 18.148); L20 (30, 18.148)-(30, 43.751); L21 (20.92, 43.407)-(20.92, 34.355); L22 (18.103, 34.298)-(18.103, 49.009); L23 (30, 55.245)-(30, 58.378); L24 (18.517, 55.245)-(30, 55.245); L25 (26.609, 70.976)-(16.319, 61.509); L26 (15, 71.913)-(26.243, 71.913); L27 (15, 75.015)-(15, 71.913); L28 (27.162, 75.015)-(15, 75.015); L29 (18.276, 59.095)-(29.376, 69.36); L30 (30, 58.378)-(18.592, 58.378); L31 (19.196, 50.102)-(30, 50.102); L32 (18.103, 34.298)-(18.103, 49.009); L33 (20.92, 43.407)-(20.92, 34.355); L34 (30, 18.148)-(30, 43.751); L35 (26.839, 18.148)-(30, 18.148); L36 (26.839, 24.557)-(26.839, 18.148); L37 (15, 24.557)-(26.839, 24.557); L38 (15, 27.66)-(15, 24.557); L39 (26.839, 27.66)-(15, 27.66); L40 (26.839, 43.35)-(26.839, 27.66); L41 (24.023, 33.838)-(24.023, 43.465); L42 (15, 49.039)-(15, 33.838); L43 (30, 53.234)-(19.196, 53.234); L44 (30, 50.102)-(30, 53.234); A1 r 0.415 centre (18.557, 58.791) between (18.276, 59.095) and (18.592, 58.378); A2 r 3.261 centre (27.162, 71.754) between (29.376, 69.36) and (27.162, 75.015); A3 r 0.54 centre (26.243, 71.373) between (26.609, 70.976) and (26.243, 71.913); A4 r 3.517 centre (18.517, 58.763) between (16.319, 61.509) and (18.517, 55.245); A5 r 4.196 centre (19.196, 49.039) between (19.196, 53.234) and (15, 49.039); A6 r 4.568 centre (19.511, 34.556) between (15, 33.838) and (24.023, 33.838); A7 r 1.41 centre (25.433, 43.465) between (26.839, 43.35) and (24.023, 43.465); A8 r 4.547 centre (25.453, 43.751) between (30, 43.751) and (20.92, 43.407); A9 r 1.417 centre (19.508, 34.478) between (18.103, 34.298) and (20.92, 34.355); A10 r 1.093 centre (19.196, 49.009) between (19.196, 50.102) and (18.103, 49.009); A11 r 3.517 centre (18.517, 58.763) between (16.319, 61.509) and (18.517, 55.245); A12 r 0.54 centre (26.243, 71.373) between (26.609, 70.976) and (26.243, 71.913); A13 r 3.261 centre (27.162, 71.754) between (29.376, 69.36) and (27.162, 75.015); A14 r 0.415 centre (18.557, 58.791) between (18.276, 59.095) and (18.592, 58.378); A15 r 1.093 centre (19.196, 49.009) between (19.196, 50.102) and (18.103, 49.009); A16 r 1.417 centre (19.508, 34.478) between (18.103, 34.298) and (20.92, 34.355); A17 r 4.547 centre (25.453, 43.751) between (30, 43.751) and (20.92, 43.407); A18 r 1.41 centre (25.433, 43.465) between (26.839, 43.35) and (24.023, 43.465); A19 r 4.568 centre (19.511, 34.556) between (15, 33.838) and (24.023, 33.838); A20 r 4.196 centre (19.196, 49.039) between (19.196, 53.234) and (15, 49.039); 1 further point
  constraints: 88 end point, 40 point on circle, 20 centre point
node "Block7:1" dims "d777" = 15, "d778" = 18.148
node "Planar Surface 2" dims "d446" = 2.3385 (derived), "d447" = 8.09976 (derived), "d525" = 52.99059 (derived), "d527" = 0.05 (derived), "d528" = 0 (derived), "d529" = 0 (derived), "d545" = 21.5915 (derived), "d547" = 0.05 (derived), "d548" = 0 (derived), "d549" = 0 (derived), "d560" = 7.29892 (derived), "d561" = 5.22182 (derived), "d562" = 0.5 (derived), "d563" = 0 (derived), "d564" = 0 (derived), "d565" = 4.43129 (derived), "d566" = 0.05984 (derived), "d567" = 0.5 (derived), "d568" = 0 (derived), "d569" = 0 (derived), "d570" = 3.72166 (derived), "d571" = 0.83718 (derived), "d572" = 0.5 (derived), "d573" = 0 (derived)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
node "Datum Identifier 2" dims "d446" = 2.3385 (derived), "d447" = 8.09976 (derived), "d525" = 52.99059 (derived), "d527" = 0.05 (derived), "d528" = 0 (derived), "d529" = 0 (derived), "d545" = 21.5915 (derived), "d547" = 0.05 (derived), "d548" = 0 (derived), "d549" = 0 (derived), "d560" = 7.29892 (derived), "d561" = 5.22182 (derived), "d562" = 0.5 (derived), "d563" = 0 (derived), "d564" = 0 (derived), "d565" = 4.43129 (derived), "d566" = 0.05984 (derived), "d567" = 0.5 (derived), "d568" = 0 (derived), "d569" = 0 (derived), "d570" = 3.72166 (derived), "d571" = 0.83718 (derived), "d572" = 0.5 (derived), "d573" = 0 (derived)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
node "Planar Surface 3" dims "d446" = 2.3385 (derived), "d447" = 8.09976 (derived), "d525" = 52.99059 (derived), "d527" = 0.05 (derived), "d528" = 0 (derived), "d529" = 0 (derived), "d545" = 21.5915 (derived), "d547" = 0.05 (derived), "d548" = 0 (derived), "d549" = 0 (derived), "d560" = 7.29892 (derived), "d561" = 5.22182 (derived), "d562" = 0.5 (derived), "d563" = 0 (derived), "d564" = 0 (derived), "d565" = 4.43129 (derived), "d566" = 0.05984 (derived), "d567" = 0.5 (derived), "d568" = 0 (derived), "d569" = 0 (derived), "d570" = 3.72166 (derived), "d571" = 0.83718 (derived), "d572" = 0.5 (derived), "d573" = 0 (derived)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
node "Planar Surface 4" dims "d446" = 2.3385 (derived), "d447" = 8.09976 (derived), "d525" = 52.99059 (derived), "d527" = 0.05 (derived), "d528" = 0 (derived), "d529" = 0 (derived), "d545" = 21.5915 (derived), "d547" = 0.05 (derived), "d548" = 0 (derived), "d549" = 0 (derived), "d560" = 7.29892 (derived), "d561" = 5.22182 (derived), "d562" = 0.5 (derived), "d563" = 0 (derived), "d564" = 0 (derived), "d565" = 4.43129 (derived), "d566" = 0.05984 (derived), "d567" = 0.5 (derived), "d568" = 0 (derived), "d569" = 0 (derived), "d570" = 3.72166 (derived), "d571" = 0.83718 (derived), "d572" = 0.5 (derived), "d573" = 0 (derived)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
node "Datum Reference Frame 4"
node "Simple Hole 1" dims "d446" = 2.3385 (derived), "d447" = 8.09976 (derived), "d525" = 52.99059 (derived), "d527" = 0.05 (derived), "d528" = 0 (derived), "d529" = 0 (derived), "d545" = 21.5915 (derived), "d547" = 0.05 (derived), "d548" = 0 (derived), "d549" = 0 (derived), "d560" = 7.29892 (derived), "d561" = 5.22182 (derived), "d562" = 0.5 (derived), "d563" = 0 (derived), "d564" = 0 (derived), "d565" = 4.43129 (derived), "d566" = 0.05984 (derived), "d567" = 0.5 (derived), "d568" = 0 (derived), "d569" = 0 (derived), "d570" = 3.72166 (derived), "d571" = 0.83718 (derived), "d572" = 0.5 (derived), "d573" = 0 (derived)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
node "Datum Reference Frame 5"
node "Datum Reference Frame 6"
node "Simple Hole 2" dims "d446" = 2.3385 (derived), "d447" = 8.09976 (derived), "d525" = 52.99059 (derived), "d527" = 0.05 (derived), "d528" = 0 (derived), "d529" = 0 (derived), "d545" = 21.5915 (derived), "d547" = 0.05 (derived), "d548" = 0 (derived), "d549" = 0 (derived), "d560" = 7.29892 (derived), "d561" = 5.22182 (derived), "d562" = 0.5 (derived), "d563" = 0 (derived), "d564" = 0 (derived), "d565" = 4.43129 (derived), "d566" = 0.05984 (derived), "d567" = 0.5 (derived), "d568" = 0 (derived), "d569" = 0 (derived), "d570" = 3.72166 (derived), "d571" = 0.83718 (derived), "d572" = 0.5 (derived), "d573" = 0 (derived)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
node "Datum Reference Frame 7"
node "Datum Reference Frame 10"
node "Planar Surface 6"
node "Planar Surface 7"
node "Hole Note 2"
node "Feature Control Frame 3"
node "Datum Identifier 12" dims "d446" = 2.3385 (derived), "d447" = 8.09976 (derived), "d525" = 52.99059 (derived), "d527" = 0.05 (derived), "d528" = 0 (derived), "d529" = 0 (derived), "d545" = 21.5915 (derived), "d547" = 0.05 (derived), "d548" = 0 (derived), "d549" = 0 (derived), "d560" = 7.29892 (derived), "d561" = 5.22182 (derived), "d562" = 0.5 (derived), "d563" = 0 (derived), "d564" = 0 (derived), "d565" = 4.43129 (derived), "d566" = 0.05984 (derived), "d567" = 0.5 (derived), "d568" = 0 (derived), "d569" = 0 (derived), "d570" = 3.72166 (derived), "d571" = 0.83718 (derived), "d572" = 0.5 (derived), "d573" = 0 (derived)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
node "Hole Note 1"
node "Feature Control Frame 2"
node "Datum Identifier 15" dims "d446" = 2.3385 (derived), "d447" = 8.09976 (derived), "d525" = 52.99059 (derived), "d527" = 0.05 (derived), "d528" = 0 (derived), "d529" = 0 (derived), "d545" = 21.5915 (derived), "d547" = 0.05 (derived), "d548" = 0 (derived), "d549" = 0 (derived), "d560" = 7.29892 (derived), "d561" = 5.22182 (derived), "d562" = 0.5 (derived), "d563" = 0 (derived), "d564" = 0 (derived), "d565" = 4.43129 (derived), "d566" = 0.05984 (derived), "d567" = 0.5 (derived), "d568" = 0 (derived), "d569" = 0 (derived), "d570" = 3.72166 (derived), "d571" = 0.83718 (derived), "d572" = 0.5 (derived), "d573" = 0 (derived)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
node "Feature Control Frame 6"
node "Datum Reference Frame 11"
node "Feature Control Frame 7"
node "Datum Reference Frame 12"
node "Planar Surface 9"
node "Feature Control Frame 19"
node "Datum Reference Frame 13"
node "Planar Surface 10"
node "Feature Control Frame 22"
node "Planar Surface 16" dims "d446" = 2.3385 (derived), "d447" = 8.09976 (derived), "d525" = 52.99059 (derived), "d527" = 0.05 (derived), "d528" = 0 (derived), "d529" = 0 (derived), "d545" = 21.5915 (derived), "d547" = 0.05 (derived), "d548" = 0 (derived), "d549" = 0 (derived), "d560" = 7.29892 (derived), "d561" = 5.22182 (derived), "d562" = 0.5 (derived), "d563" = 0 (derived), "d564" = 0 (derived), "d565" = 4.43129 (derived), "d566" = 0.05984 (derived), "d567" = 0.5 (derived), "d568" = 0 (derived), "d569" = 0 (derived), "d570" = 3.72166 (derived), "d571" = 0.83718 (derived), "d572" = 0.5 (derived), "d573" = 0 (derived)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
node "Datum Identifier 19" dims "d446" = 2.3385 (derived), "d447" = 8.09976 (derived), "d525" = 52.99059 (derived), "d527" = 0.05 (derived), "d528" = 0 (derived), "d529" = 0 (derived), "d545" = 21.5915 (derived), "d547" = 0.05 (derived), "d548" = 0 (derived), "d549" = 0 (derived), "d560" = 7.29892 (derived), "d561" = 5.22182 (derived), "d562" = 0.5 (derived), "d563" = 0 (derived), "d564" = 0 (derived), "d565" = 4.43129 (derived), "d566" = 0.05984 (derived), "d567" = 0.5 (derived), "d568" = 0 (derived), "d569" = 0 (derived), "d570" = 3.72166 (derived), "d571" = 0.83718 (derived), "d572" = 0.5 (derived), "d573" = 0 (derived)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
node "Datum Reference Frame 20"
node "Datum Reference Frame 21"
node "Simple Hole 11"
node "Simple Hole 12"
node "Diameter Dimension 4" dims "d691" = 100 (derived)
node "Feature Control Frame 32"
node "Planar Surface 17"
node "Feature Control Frame 33"
node "Planar Surface 18"
node "Planar Surface 19"
node "Planar Surface 20"
node "General Note 1"
node "Planar Surface 22" dims "d446" = 2.3385 (derived), "d447" = 8.09976 (derived), "d525" = 52.99059 (derived), "d527" = 0.05 (derived), "d528" = 0 (derived), "d529" = 0 (derived), "d545" = 21.5915 (derived), "d547" = 0.05 (derived), "d548" = 0 (derived), "d549" = 0 (derived), "d560" = 7.29892 (derived), "d561" = 5.22182 (derived), "d562" = 0.5 (derived), "d563" = 0 (derived), "d564" = 0 (derived), "d565" = 4.43129 (derived), "d566" = 0.05984 (derived), "d567" = 0.5 (derived), "d568" = 0 (derived), "d569" = 0 (derived), "d570" = 3.72166 (derived), "d571" = 0.83718 (derived), "d572" = 0.5 (derived), "d573" = 0 (derived)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
node "Datum Identifier 23" dims "d446" = 2.3385 (derived), "d447" = 8.09976 (derived), "d525" = 52.99059 (derived), "d527" = 0.05 (derived), "d528" = 0 (derived), "d529" = 0 (derived), "d545" = 21.5915 (derived), "d547" = 0.05 (derived), "d548" = 0 (derived), "d549" = 0 (derived), "d560" = 7.29892 (derived), "d561" = 5.22182 (derived), "d562" = 0.5 (derived), "d563" = 0 (derived), "d564" = 0 (derived), "d565" = 4.43129 (derived), "d566" = 0.05984 (derived), "d567" = 0.5 (derived), "d568" = 0 (derived), "d569" = 0 (derived), "d570" = 3.72166 (derived), "d571" = 0.83718 (derived), "d572" = 0.5 (derived), "d573" = 0 (derived)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
node "Datum Reference Frame 27"
node "Simple Hole 16"
node "Datum Identifier 24" dims "d446" = 2.3385 (derived), "d447" = 8.09976 (derived), "d525" = 52.99059 (derived), "d527" = 0.05 (derived), "d528" = 0 (derived), "d529" = 0 (derived), "d545" = 21.5915 (derived), "d547" = 0.05 (derived), "d548" = 0 (derived), "d549" = 0 (derived), "d560" = 7.29892 (derived), "d561" = 5.22182 (derived), "d562" = 0.5 (derived), "d563" = 0 (derived), "d564" = 0 (derived), "d565" = 4.43129 (derived), "d566" = 0.05984 (derived), "d567" = 0.5 (derived), "d568" = 0 (derived), "d569" = 0 (derived), "d570" = 3.72166 (derived), "d571" = 0.83718 (derived), "d572" = 0.5 (derived), "d573" = 0 (derived)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
node "Feature Control Frame 36"
node "Feature Control Frame 35"
node "Feature Control Frame 34"
node "Hole Note 13"
node "Feature Control Frame 51"
node "Feature Control Frame 57" dims "d446" = 2.3385 (derived), "d447" = 8.09976 (derived), "d525" = 52.99059 (derived), "d527" = 0.05 (derived), "d528" = 0 (derived), "d529" = 0 (derived), "d545" = 21.5915 (derived), "d547" = 0.05 (derived), "d548" = 0 (derived), "d549" = 0 (derived), "d560" = 7.29892 (derived), "d561" = 5.22182 (derived), "d562" = 0.5 (derived), "d563" = 0 (derived), "d564" = 0 (derived), "d565" = 4.43129 (derived), "d566" = 0.05984 (derived), "d567" = 0.5 (derived), "d568" = 0 (derived), "d569" = 0 (derived), "d570" = 3.72166 (derived), "d571" = 0.83718 (derived), "d572" = 0.5 (derived), "d573" = 0 (derived)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
node "Datum Identifier 29" dims "d446" = 2.3385 (derived), "d447" = 8.09976 (derived), "d525" = 52.99059 (derived), "d527" = 0.05 (derived), "d528" = 0 (derived), "d529" = 0 (derived), "d545" = 21.5915 (derived), "d547" = 0.05 (derived), "d548" = 0 (derived), "d549" = 0 (derived), "d560" = 7.29892 (derived), "d561" = 5.22182 (derived), "d562" = 0.5 (derived), "d563" = 0 (derived), "d564" = 0 (derived), "d565" = 4.43129 (derived), "d566" = 0.05984 (derived), "d567" = 0.5 (derived), "d568" = 0 (derived), "d569" = 0 (derived), "d570" = 3.72166 (derived), "d571" = 0.83718 (derived), "d572" = 0.5 (derived), "d573" = 0 (derived)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
node "Diameter Dimension 5" dims "d987" = 22 (derived)
node "Diameter Dimension 6" dims "d1008" = 22 (derived)
other parameters: "d176" = 215, "d184" = -15, "d315" = 0, "d361" = -81, "d676" = 0, "d789" = -25, "d790" = 0, "d791" = 0, "d792" = 0, "d793" = 0, "d794" = 90 deg, "d795" = 0, "d796" = 0, "d797" = 0, "d798" = 0, "d799" = -90 deg, "d800" = -90 deg, "d811" = 0, "d812" = 0, "d813" = 0, "d814" = 0, "d815" = -180 deg, "d816" = 0, "d821" = 0, "d822" = 0, "d823" = 0, "d824" = 0, "d825" = -180 deg, "d826" = 0
